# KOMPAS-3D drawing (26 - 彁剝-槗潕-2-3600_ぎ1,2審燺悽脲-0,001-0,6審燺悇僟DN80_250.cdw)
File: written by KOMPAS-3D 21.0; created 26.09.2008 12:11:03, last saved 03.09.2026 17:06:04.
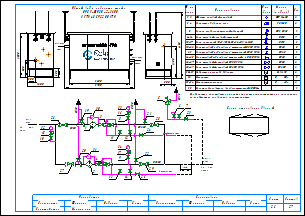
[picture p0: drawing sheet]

Sheets 1-2: A3, landscape

Document properties: Наименование: Макро:21; Автор: RaskoAdmin; Форматы листов документа: 2xA3; Полное имя файла: \\UR38nt01\Departments\КТО\КБ ПУРДГ\Заявки\Прайс-лист на типовые шкафы ГРПШ\ПРДГ_стандарт_20_03_2026\ПРДГ с РДГ(Н, В)\ПРДГ-ШУЭО-2-3600_до1,2МПа_Рвых-0,001-0,6МПа_РДГ_DN80_250.cdw

Title block, sheet 1: Наименование: Пункт учета газа / ПУГ-Ш-400-Р / ЛГТИ.485922.001ТУ; designation: ЛГТИ.03.4411141; sheet number: 1; Количество листов документа: 2; organisation: ООО "ЭЛЬСТЕР Газэлектроника"; Форматы листов документа: A3; stored path: C:\Рабочие документы\Компас\ПУГ\Схема.cdw; Разработал: Устинов; Проверил: Кошкин; Утвердил: Кошкин
Title block, sheet 2: sheet number: 2; stored path: D:\Рабочие документы\Заявки\ПУРДГ\ПУРДГ-ШУЭО-2-100-Р 4411220.cdw; designation, second copy: ЛГТИ.03.4411141-

Views: Вид 1, Вид 2
Referenced files: wcvoit.frw
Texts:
  Normal
  № на
  схеме
  Усл.
  обозн.
  Марка
  (модель)
  Кол.
  Фильтр газовый фланцевый
  ФГ 16-80
  Регулятор давления газа
  РДГ-50
  Клапан предохранительный сбросной
  ПСК DN25
  Кран шаровой газовый латунный
  DN15
  Кран кнопочный VE-РАСКО-НЗ-1,6-G1/2-М20
  Кран шаровой "под приварку" штуцерный DN20 PN16
  Кран шаровой "под приварку" штуцерный DN25 PN16
  Кран шаровой "под приварку" штуцерный п/п DN20 PN16
  DN20
  DN25
  Кран шаровой фланцевый DN80 PN16
  Кран шаровой фланцевый DN250 PN16
  DN80
  DN250
  Индикатор перепада давления
  Delta 15
  Манометр
  Манометр-напоромер
  Электрообогреватель взрывозащищенный 2000Вт
  0...     МПа
  0...     кПа
  Общий вид и габариты шкафа
  ПРДГ-ШУЭО-2-3600
  Выход газа
  Вход газа
  logo-rasko-ge.png
  Вход
  газа
  PDI
  Выход
  Р=     кПа
  DN50
  Импульс DN20
  ≥5DN
  HYSWLongFangSong
  Р=       МПа
  Схема открывания дверей
  Предприятие изготовитель может заменять комплектующие на аналогичные,
  не ухудшающие заявленных характеристик.
  Должность
  Конструктор
  Фамилия
  Подпись
  Дата
  Согласовано
  Максимкин
  Лист
  Листов
  POLYLINE_STYLE_0.18_RGB_0_0_0
  POLYLINE_STYLE_0.50_RGB_0_0_0
  POLYLINE_STYLE_0.34_RGB_0_0_0
  PHANTOM_RGB_0_0_0_SC_1_THICK_0.18
  K5LT_THIN_RGB_0_0_0_THICK_0.18
  K5LT32769_RGB_0_0_0_THICK_0.18
  K5LT12_RGB_0_0_0_SC_1_THICK_0.18
  K5LT_DASHED_RGB_0_0_0_SC_1_THICK_0.18
  ACISOTGL_RGB_0_0_0_SC_0.8_THICK_0.25
  CONTINUOUS_RGB_0_127_31_THICK_0.3
  CONTINUOUS_RGB_0_0_255_THICK_0.35
  CONTINUOUS_RGB_255_0_0_THICK_0.35
  POLYLINE_STYLE_0.25_RGB_0_0_0
  CONTINUOUS_RGB_0_0_0_THICK_0.5
  POLYLINE_STYLE_0.35_RGB_0_0_255
  CONTINUOUS_RGB_0_0_0_THICK_0.4
  CONTINUOUS_RGB_0_0_0_THICK_0.35
  Без оформления
Dimensions and other numbers on the sheet: 1; 1, 2; 2; 3, 4; 5; 6-14; 9; 15-17; 3; 18-22; 23; 24-25; 26-27; 28-29; 30-31; 32; 33-34; 35; 500; 1200; 305; 2000; 3900; 4130; 3600; 4; 10; 27; 28; 29; 8; 12; 19; 20; 21; 22; 25; 24; 30; 31; 15; 16; 26; 6; 7; 11; 14; 13; 33; 17; 34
